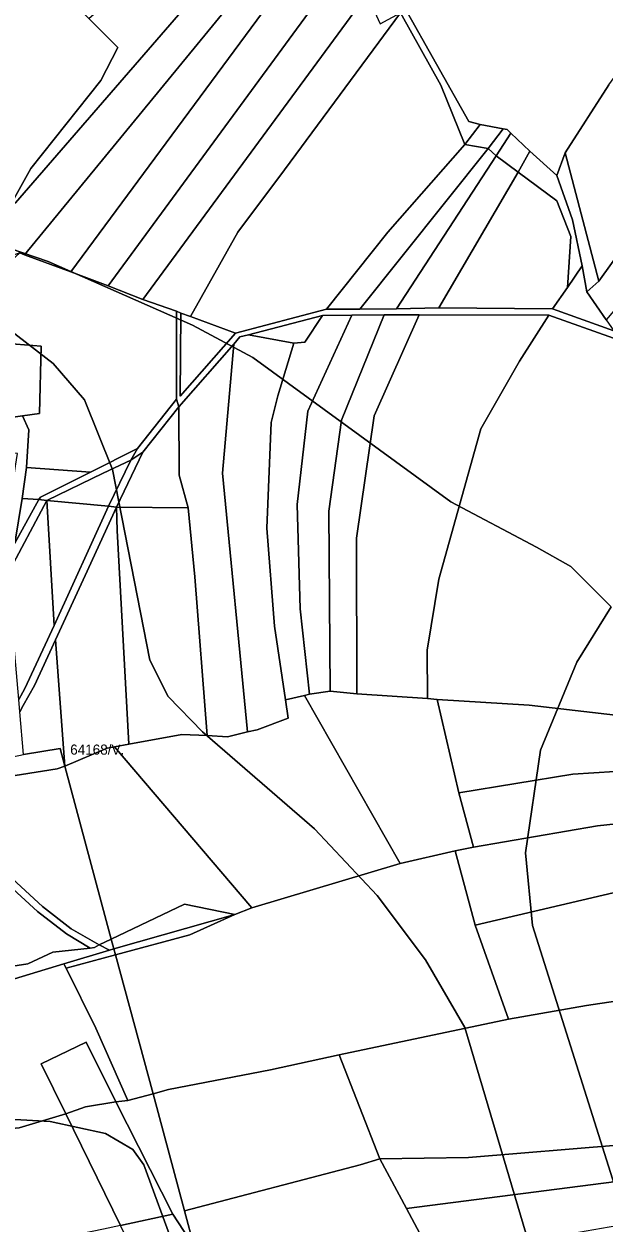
# Model space of a CAD drawing. Extents: x -521261 to -517465, y -1182764 to -1179456.
# Drawn here: x -519202 to -518915, y -1181121 to -1180527 of the extents above; entities that cross this region are included whole.
import ezdxf

# ---------------------------------------------------------------- set-up
doc = ezdxf.new("R2010")
doc.units = 0
for name, color, linetype in [('95560013', 7, 'Continuous'), ('95610013', 7, 'Continuous'), ('95640013', 7, 'Continuous'), ('95660013', 7, 'Continuous')]:
    doc.layers.add(name, color=color, linetype=linetype)

msp = doc.modelspace()

# ---------------------------------------------------------------- linework, layer by layer
at = {"layer": '95560013'}
for points in [[(-518912.15, -1180557.37), (-518933.81, -1180591.04), (-518938.01, -1180602.29), (-518951.28, -1180590.32), (-518960.78, -1180581.34), (-518962.6, -1180579.56), (-518964.48, -1180579.13), (-518975.87, -1180577.02), (-518981.52, -1180575.61), (-519013.54, -1180518.68), (-519017.95, -1180511.02), (-519021.16, -1180506.1), (-519008.28, -1180481.84), (-518988.53, -1180447.41), (-518966.24, -1180412.4), (-518924.13, -1180356.64), (-518872.62, -1180293.06)], [(-518909.82, -1180682.93), (-518941.97, -1180671.51), (-519006.2, -1180671.38), (-519023.52, -1180671.3), (-519039.43, -1180671.57), (-519054.1, -1180671.71), (-519090.68, -1180681.2), (-519094.95, -1180682.3), (-519098.03, -1180685.92), (-519125.2, -1180716.99), (-519126.28, -1180713.17), (-519126.4, -1180669.56), (-519124.23, -1180670.51), (-519124.54, -1180711.6), (-519097.2, -1180680.42), (-519052.05, -1180668.61), (-519035.6, -1180668.57), (-519017.31, -1180668.38), (-518996.34, -1180667.9), (-518940.14, -1180668.41), (-518909.75, -1180679.28)], [(-518812.84, -1180997.02), (-518923.19, -1181013.55), (-518961.94, -1181020.33), (-518978.45, -1180973.7), (-518851.55, -1180944.12)]]:
    msp.add_lwpolyline(points, dxfattribs=at)
for points in [[(-519074.75, -1180441.61), (-519066.1, -1180454.21), (-519206.13, -1180615.83), (-519210.1, -1180619.68), (-519198.46, -1180598.79), (-519163.85, -1180555.26), (-519155.37, -1180538.92), (-519169.7, -1180524.6)], [(-519233.13, -1180450.99), (-519223.33, -1180463.53), (-519206.92, -1180483.41), (-519189.37, -1180503.99), (-519169.7, -1180524.6), (-519155.37, -1180538.92), (-519163.85, -1180555.26), (-519198.46, -1180598.79), (-519210.1, -1180619.68), (-519214.62, -1180628.5), (-519220.68, -1180646.69), (-519235.13, -1180645.15), (-519284.06, -1180641.39), (-519293.11, -1180638.89)], [(-519066.1, -1180454.21), (-519057.81, -1180466.19), (-519201.63, -1180641.6), (-519204, -1180640.65), (-519220.68, -1180646.69), (-519214.62, -1180628.5), (-519210.1, -1180619.68), (-519206.13, -1180615.83)], [(-519057.81, -1180466.19), (-519050.56, -1180476.44), (-519178.7, -1180650.07), (-519201.63, -1180641.6)], [(-519050.56, -1180476.44), (-519047.53, -1180480.71), (-519040.51, -1180493.58), (-519160.17, -1180656.97), (-519178.7, -1180650.07)], [(-519040.51, -1180493.58), (-519032.04, -1180512.65), (-519143, -1180663.69), (-519160.17, -1180656.97)], [(-519025.42, -1180527.18), (-519015.39, -1180521.74), (-519072.92, -1180599.44), (-519095.94, -1180630.44), (-519119.41, -1180672.22), (-519124.23, -1180670.51), (-519126.4, -1180669.56), (-519143, -1180663.69), (-519032.04, -1180512.65)], [(-518995.4, -1180557.56), (-518983.49, -1180586.91), (-519021.63, -1180630.34), (-519052.05, -1180668.61), (-519097.2, -1180680.42), (-519119.41, -1180672.22), (-519095.94, -1180630.44), (-519072.92, -1180599.44), (-519015.39, -1180521.74)], [(-518887.35, -1180523.29), (-518879.8, -1180531.46), (-518844.2, -1180566.48), (-518849.54, -1180575.21), (-518903.85, -1180636.05), (-518917.08, -1180654.6), (-518933.81, -1180591.04), (-518912.15, -1180557.37)], [(-518832.97, -1180577.12), (-518832.02, -1180577.88), (-518913.54, -1180673.81), (-518923.11, -1180660.01), (-518917.08, -1180654.6), (-518903.85, -1180636.05), (-518849.54, -1180575.21)], [(-518971.94, -1180589.02), (-519035.6, -1180668.57), (-519052.05, -1180668.61), (-519021.63, -1180630.34), (-518983.49, -1180586.91)], [(-518967.98, -1180592.51), (-519017.31, -1180668.38), (-519035.6, -1180668.57), (-518971.94, -1180589.02)], [(-518933.81, -1180591.04), (-518917.08, -1180654.6), (-518923.11, -1180660.01), (-518925.35, -1180647.03), (-518930.19, -1180624.23), (-518938.01, -1180602.29)], [(-518957.18, -1180600.74), (-518996.34, -1180667.9), (-519017.31, -1180668.38), (-518967.98, -1180592.51)], [(-518938.04, -1180614.84), (-518931.02, -1180632.55), (-518932.61, -1180657.78), (-518940.14, -1180668.41), (-518996.34, -1180667.9), (-518957.18, -1180600.74)], [(-519201.63, -1180641.6), (-519178.7, -1180650.07), (-519160.17, -1180656.97), (-519143, -1180663.69), (-519126.4, -1180669.56), (-519126.28, -1180713.17), (-519145.75, -1180737.67), (-519169.01, -1180749.28), (-519200.67, -1180746.94), (-519199.44, -1180728.39), (-519202.56, -1180721.35), (-519194.14, -1180720.3), (-519193.43, -1180686.91), (-519214.15, -1180685.3), (-519219.9, -1180697.33), (-519215.32, -1180723.28), (-519229.69, -1180664.25), (-519204, -1180640.65)], [(-519119.41, -1180672.22), (-519097.2, -1180680.42), (-519124.54, -1180711.6), (-519124.23, -1180670.51)], [(-519090.68, -1180681.2), (-519054.1, -1180671.71), (-519062.82, -1180684.94), (-519068.27, -1180685.34)], [(-519054.1, -1180671.71), (-519039.43, -1180671.57), (-519061.22, -1180719.04), (-519066.54, -1180765.31), (-519065.15, -1180816.97), (-519060.47, -1180859.25), (-519062.91, -1180859.99), (-519072.36, -1180862.15), (-519077.87, -1180825.57), (-519081.64, -1180777.01), (-519079.39, -1180724.68), (-519076.23, -1180711.49), (-519068.27, -1180685.34), (-519062.82, -1180684.94)], [(-519039.43, -1180671.57), (-519023.52, -1180671.3), (-519044.65, -1180723.59), (-519050.95, -1180768.66), (-519050.24, -1180857.78), (-519060.47, -1180859.25), (-519065.15, -1180816.97), (-519066.54, -1180765.31), (-519061.22, -1180719.04)], [(-519023.52, -1180671.3), (-519006.2, -1180671.38), (-519028.47, -1180721.44), (-519037.22, -1180782.06), (-519036.99, -1180859.16), (-519050.24, -1180857.78), (-519050.95, -1180768.66), (-519044.65, -1180723.59)], [(-519006.2, -1180671.38), (-518941.97, -1180671.51), (-518956.42, -1180694.36), (-518975.66, -1180727.8), (-518996.34, -1180802.27), (-519002.23, -1180837.59), (-519002.07, -1180861.48), (-519036.99, -1180859.16), (-519037.22, -1180782.06), (-519028.47, -1180721.44)], [(-518941.97, -1180671.51), (-518909.82, -1180682.93), (-518875.99, -1180713.85), (-518845.74, -1180742.65), (-518833.61, -1180758.15), (-518832.03, -1180758.37), (-518817.62, -1180777.25), (-518864.92, -1180826.18), (-518886.25, -1180852.47), (-518897.52, -1180871.08), (-518951.62, -1180864.77), (-518997.23, -1180861.95), (-519002.07, -1180861.48), (-519002.23, -1180837.59), (-518996.34, -1180802.27), (-518975.66, -1180727.8), (-518956.42, -1180694.36)], [(-519125.2, -1180716.99), (-519098.03, -1180685.92), (-519103.52, -1180749.76), (-519091.1, -1180878.03), (-519101.1, -1180880.53), (-519111.23, -1180879.85), (-519117.2, -1180801.11), (-519120.61, -1180767), (-519124.99, -1180750.86)], [(-519094.95, -1180682.3), (-519090.68, -1180681.2), (-519068.27, -1180685.34), (-519076.23, -1180711.49), (-519079.39, -1180724.68), (-519081.64, -1180777.01), (-519077.87, -1180825.57), (-519072.36, -1180862.15), (-519071.05, -1180871.19), (-519086.46, -1180877.01), (-519091.1, -1180878.03), (-519103.52, -1180749.76), (-519098.03, -1180685.92)], [(-519209.92, -1180799.66), (-519190.52, -1180763.31), (-519186.92, -1180825.27), (-519201.54, -1180856.5), (-519204.52, -1180861.93)], [(-519190.52, -1180763.31), (-519160.03, -1180766.24), (-519186.92, -1180825.27)], [(-519160.03, -1180766.24), (-519156.02, -1180766.62), (-519171.55, -1180800.59), (-519186.23, -1180832.37), (-519196.72, -1180855.04), (-519202.24, -1180864.93), (-519203.98, -1180868.12), (-519204.52, -1180861.93), (-519201.54, -1180856.5), (-519186.92, -1180825.27)], [(-519156.02, -1180766.62), (-519155.75, -1180778.14), (-519149.92, -1180884.09), (-519156.98, -1180885.41), (-519160.74, -1180886.13), (-519181.69, -1180894.95), (-519186.23, -1180832.37), (-519171.55, -1180800.59)], [(-519156.02, -1180766.62), (-519120.61, -1180767), (-519117.2, -1180801.11), (-519111.23, -1180879.85), (-519123.64, -1180879.36), (-519149.92, -1180884.09), (-519155.75, -1180778.14)], [(-519186.23, -1180832.37), (-519181.69, -1180894.95), (-519184.03, -1180886.23), (-519202.16, -1180889.15), (-519203.98, -1180868.12), (-519202.24, -1180864.93), (-519196.72, -1180855.04)], [(-519050.24, -1180857.78), (-519036.99, -1180859.16), (-519002.07, -1180861.48), (-518997.23, -1180861.95), (-518986.46, -1180908.17), (-518979.29, -1180935.1), (-518988.33, -1180936.99), (-519015.48, -1180943.14), (-519062.91, -1180859.99), (-519060.47, -1180859.25)], [(-519062.91, -1180859.99), (-519015.48, -1180943.14), (-519089.11, -1180965.2), (-519156.98, -1180885.41), (-519149.92, -1180884.09), (-519123.64, -1180879.36), (-519111.23, -1180879.85), (-519101.1, -1180880.53), (-519091.1, -1180878.03), (-519086.46, -1180877.01), (-519071.05, -1180871.19), (-519072.36, -1180862.15)], [(-518997.23, -1180861.95), (-518951.62, -1180864.77), (-518897.52, -1180871.08), (-518879.81, -1180872.74), (-518898.78, -1180896.9), (-518930.07, -1180899.02), (-518986.46, -1180908.17)], [(-519156.98, -1180885.41), (-519089.11, -1180965.2), (-519097.48, -1180968.4), (-519122.43, -1180963.43), (-519158.63, -1180980.64), (-519181.69, -1180894.95), (-519160.74, -1180886.13)], [(-518930.07, -1180899.02), (-518898.78, -1180896.9), (-518905.31, -1180905.29), (-518883.79, -1180920.87), (-518917.86, -1180924.58), (-518979.29, -1180935.1), (-518986.46, -1180908.17)], [(-518883.79, -1180920.87), (-518851.55, -1180944.12), (-518978.45, -1180973.7), (-518988.33, -1180936.99), (-518979.29, -1180935.1), (-518917.86, -1180924.58)], [(-518988.33, -1180936.99), (-518978.45, -1180973.7), (-518961.94, -1181020.33), (-519045.75, -1181037.98), (-519079.81, -1181045.41), (-519130.37, -1181055.19), (-519137.92, -1181057.32), (-519156.53, -1180988.48), (-519119.73, -1180978.56), (-519097.48, -1180968.4), (-519089.11, -1180965.2), (-519015.48, -1180943.14)], [(-519097.48, -1180968.4), (-519157.34, -1180985.46), (-519158.63, -1180980.64), (-519122.43, -1180963.43)], [(-519119.73, -1180978.56), (-519156.53, -1180988.48), (-519157.34, -1180985.46), (-519097.48, -1180968.4)], [(-518812.84, -1180997.02), (-518826.01, -1181016.52), (-518849.41, -1181057.59), (-518856.76, -1181073.68), (-518876.41, -1181077.08), (-518905.87, -1181082.66), (-518981.74, -1181088.87), (-519025.58, -1181089.49), (-519045.75, -1181037.98), (-518961.94, -1181020.33), (-518923.19, -1181013.55)], [(-519045.75, -1181037.98), (-519025.58, -1181089.49), (-519035.38, -1181092.59), (-519122.38, -1181115.36), (-519137.92, -1181057.32), (-519130.37, -1181055.19), (-519079.81, -1181045.41)], [(-518905.87, -1181082.66), (-518876.41, -1181077.08), (-518880.14, -1181097.21), (-519012.49, -1181114.11), (-519025.58, -1181089.49), (-518981.74, -1181088.87)], [(-519025.58, -1181089.49), (-519012.49, -1181114.11), (-518999.4, -1181138.6), (-519018.65, -1181142.26), (-519067.69, -1181158.36), (-519105.92, -1181156.17), (-519117.61, -1181133.12), (-519122.38, -1181115.36), (-519035.38, -1181092.59)], [(-519012.49, -1181114.11), (-518880.14, -1181097.21), (-518883.71, -1181118.34), (-518889.2, -1181119.44), (-518999.4, -1181138.6)]]:
    msp.add_lwpolyline(points, close=True, dxfattribs=at)
at = {"layer": '95610013'}
for points in [[(-519202.77, -1180762.35), (-519194.48, -1180762.88), (-519206.36, -1180784.55)], [(-519185.49, -1180896.3), (-519181.69, -1180894.95), (-519158.63, -1180980.64), (-519164.64, -1180983.49), (-519178.57, -1180975.54), (-519192.74, -1180964.52), (-519250.72, -1180911.24), (-519241.56, -1180908.49), (-519225.65, -1180904.08), (-519213.45, -1180900.71)], [(-519254.39, -1180912.8), (-519195.15, -1180967.02), (-519180.85, -1180978), (-519169.15, -1180985.21), (-519187.6, -1180987.07), (-519199.91, -1180992.98), (-519217.21, -1180995.57), (-519257.44, -1180913.87)], [(-519159.55, -1180986.13), (-519157.34, -1180985.46), (-519156.53, -1180988.48), (-519181.06, -1180995.1), (-519182.22, -1180992.98)], [(-519181.06, -1180995.1), (-519156.53, -1180988.48), (-519137.92, -1181057.32), (-519150.38, -1181060.65), (-519166.35, -1181024.88)], [(-519182.22, -1180992.98), (-519181.06, -1180995.1), (-519166.35, -1181024.88), (-519150.38, -1181060.65), (-519156.38, -1181061.23), (-519171.09, -1181031.72), (-519193.42, -1181042.39), (-519181.18, -1181067.29), (-519204.23, -1181074.2), (-519225.06, -1181076.01), (-519247.43, -1181016.2), (-519285.29, -1181026.99), (-519291.68, -1181027.34), (-519261.07, -1181016.81)], [(-519150.38, -1181060.65), (-519137.92, -1181057.32), (-519122.38, -1181115.36), (-519117.61, -1181133.12), (-519128.11, -1181116.88), (-519156.38, -1181061.23)], [(-519204.23, -1181074.2), (-519181.18, -1181067.29), (-519154.06, -1181122.61), (-519162.47, -1181124.46), (-519185.03, -1181128.98), (-519203.9, -1181132.63), (-519230.19, -1181136.99), (-519236.78, -1181138.21), (-519240.2, -1181127.43), (-519265.48, -1181135.31), (-519268.33, -1181136.35), (-519272.32, -1181124.33), (-519282.57, -1181092.81), (-519244.79, -1181081.1), (-519235.13, -1181077.29), (-519225.06, -1181076.01)]]:
    msp.add_lwpolyline(points, close=True, dxfattribs=at)
at = {"layer": '95640013'}
for points in [[(-519015.39, -1180521.74), (-519013.54, -1180518.68), (-518981.52, -1180575.61), (-518975.87, -1180577.02), (-518983.49, -1180586.91), (-518995.4, -1180557.56)], [(-518964.48, -1180579.13), (-518971.94, -1180589.02), (-518983.49, -1180586.91), (-518975.87, -1180577.02)], [(-518962.6, -1180579.56), (-518960.78, -1180581.34), (-518967.98, -1180592.51), (-518971.94, -1180589.02), (-518964.48, -1180579.13)], [(-518951.28, -1180590.32), (-518957.18, -1180600.74), (-518967.98, -1180592.51), (-518960.78, -1180581.34)], [(-518951.28, -1180590.32), (-518938.01, -1180602.29), (-518930.19, -1180624.23), (-518925.35, -1180647.03), (-518932.61, -1180657.78), (-518931.02, -1180632.55), (-518938.04, -1180614.84), (-518957.18, -1180600.74)], [(-518932.61, -1180657.78), (-518925.35, -1180647.03), (-518923.11, -1180660.01), (-518913.54, -1180673.81), (-518909.75, -1180679.28), (-518940.14, -1180668.41)], [(-519214.15, -1180685.3), (-519193.43, -1180686.91), (-519194.14, -1180720.3), (-519202.56, -1180721.35), (-519215.32, -1180723.28), (-519219.9, -1180697.33)], [(-519126.28, -1180713.17), (-519125.2, -1180716.99), (-519143.06, -1180739.4), (-519149.03, -1180743.42), (-519145.75, -1180737.67)], [(-519202.56, -1180721.35), (-519199.44, -1180728.39), (-519200.67, -1180746.94), (-519202.77, -1180762.35), (-519206.36, -1180784.55), (-519212.62, -1180796.67), (-519208.14, -1180761.67), (-519207.07, -1180753.38), (-519206.18, -1180746.33), (-519205.19, -1180740.03), (-519210.99, -1180739.39), (-519215.32, -1180723.28)], [(-519125.2, -1180716.99), (-519124.99, -1180750.86), (-519120.61, -1180767), (-519156.02, -1180766.62), (-519143.06, -1180739.4)], [(-519149.03, -1180743.42), (-519162.67, -1180749.81), (-519190.52, -1180763.31), (-519194.48, -1180762.88), (-519193.79, -1180761.63), (-519169.01, -1180749.28), (-519145.75, -1180737.67)], [(-519143.06, -1180739.4), (-519156.02, -1180766.62), (-519160.03, -1180766.24), (-519149.03, -1180743.42)], [(-519149.03, -1180743.42), (-519160.03, -1180766.24), (-519190.52, -1180763.31), (-519162.67, -1180749.81)], [(-519200.67, -1180746.94), (-519169.01, -1180749.28), (-519193.79, -1180761.63), (-519194.48, -1180762.88), (-519202.77, -1180762.35)], [(-519194.48, -1180762.88), (-519190.52, -1180763.31), (-519209.92, -1180799.66), (-519218.18, -1180814.87), (-519218.81, -1180807.9), (-519212.62, -1180796.67), (-519206.36, -1180784.55)], [(-519184.03, -1180886.23), (-519181.69, -1180894.95), (-519185.49, -1180896.3), (-519213.45, -1180900.71), (-519213.96, -1180891.71), (-519202.16, -1180889.15)], [(-519250.72, -1180911.24), (-519192.74, -1180964.52), (-519178.57, -1180975.54), (-519164.64, -1180983.49), (-519167.01, -1180984.82), (-519169.15, -1180985.21), (-519180.85, -1180978), (-519195.15, -1180967.02), (-519254.39, -1180912.8)], [(-519167.01, -1180984.82), (-519164.64, -1180983.49), (-519159.55, -1180986.13), (-519182.22, -1180992.98), (-519261.07, -1181016.81), (-519265.89, -1181006.88), (-519253.85, -1181000.02), (-519239.59, -1181001.51), (-519230.03, -1180998.72), (-519217.21, -1180995.57), (-519199.91, -1180992.98), (-519187.6, -1180987.07), (-519169.15, -1180985.21)], [(-519158.63, -1180980.64), (-519157.34, -1180985.46), (-519159.55, -1180986.13), (-519164.64, -1180983.49)], [(-519171.09, -1181031.72), (-519156.38, -1181061.23), (-519171.43, -1181063.76), (-519181.18, -1181067.29), (-519193.42, -1181042.39)], [(-519171.43, -1181063.76), (-519156.38, -1181061.23), (-519128.11, -1181116.88), (-519154.06, -1181122.61), (-519181.18, -1181067.29)], [(-519154.06, -1181122.61), (-519128.11, -1181116.88), (-519117.61, -1181133.12), (-519111.04, -1181157.52), (-519120.66, -1181160.93), (-519112.96, -1181184.29), (-519108.73, -1181191.36), (-519119.41, -1181193.2)]]:
    msp.add_lwpolyline(points, close=True, dxfattribs=at)
at = {"layer": '95660013'}
for points in [[(-518911, -1180816), (-518931, -1180796), (-518948, -1180786.5), (-518990.5, -1180764), (-519088.5, -1180692.5), (-519118.5, -1180676.5), (-519190, -1180645), (-519233.5, -1180630), (-519359, -1180589.5), (-519368, -1180584), (-519383.5, -1180567.5), (-519420, -1180508)], [(-519233.5, -1180630), (-519190, -1180645), (-519118.5, -1180676.5), (-519088.5, -1180692.5), (-518990.5, -1180764), (-518948, -1180786.5), (-518931, -1180796), (-518911, -1180816), (-518928, -1180843.5), (-518946, -1180887), (-518953.5, -1180938), (-518950, -1180974), (-518906.5, -1181112)], [(-518951.5, -1181132.5), (-518983.5, -1181024.5), (-519003, -1180991), (-519027, -1180959), (-519058, -1180926), (-519113.5, -1180878), (-519130.5, -1180860.5), (-519139.5, -1180842.5), (-519158, -1180748), (-519172, -1180713.5), (-519187.5, -1180695.5), (-519210, -1180678)], [(-519210, -1180678), (-519187.5, -1180695.5), (-519172, -1180713.5), (-519158, -1180748), (-519139.5, -1180842.5), (-519130.5, -1180860.5), (-519113.5, -1180878), (-519058, -1180926), (-519027, -1180959), (-519003, -1180991), (-518983.5, -1181024.5), (-518951.5, -1181132.5)], [(-518906.5, -1181112), (-518950, -1180974), (-518953.5, -1180938), (-518946, -1180887), (-518928, -1180843.5), (-518911, -1180816)], [(-519224, -1181069), (-519189, -1181071), (-519161.5, -1181077), (-519148, -1181085), (-519142.5, -1181092.5), (-519127.5, -1181133.5)], [(-519127.5, -1181133.5), (-519142.5, -1181092.5), (-519148, -1181085), (-519161.5, -1181077), (-519189, -1181071), (-519224, -1181069)]]:
    msp.add_lwpolyline(points, dxfattribs=at)

# ---------------------------------------------------------------- texts
msp.add_text('64168/V.', height=5, rotation=360, dxfattribs=at).set_placement((-519179, -1180889.28))

doc.saveas('drawing.dxf')
